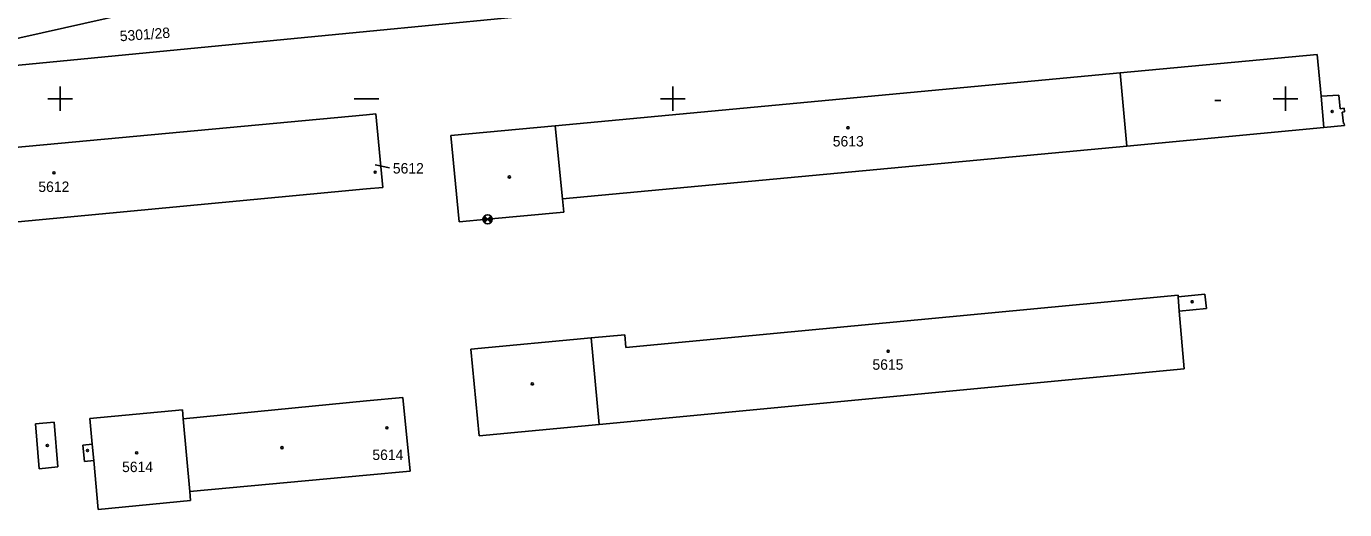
# Model space of a CAD drawing. Extents: x -822293 to -820259, y -1071573 to -1068794.
# Drawn here: x -821305.5 to -821090.3, y -1069967.1 to -1069888.2 of the extents above; entities that cross this region are included whole.
import ezdxf

# ---------------------------------------------------------------- set-up
doc = ezdxf.new("R2010")
doc.units = 0
for name, color, linetype in [('Vrstva 1', 7, 'Continuous'), ('Vrstva 10', 7, 'Continuous'), ('Vrstva 13', 7, 'Continuous'), ('Vrstva 18', 7, 'Continuous'), ('Vrstva 19', 7, 'Continuous'), ('Vrstva 2', 7, 'Continuous'), ('Vrstva 24', 7, 'Continuous'), ('Vrstva 25', 7, 'Continuous'), ('Vrstva 3', 7, 'Continuous'), ('Vrstva 62', 7, 'Continuous')]:
    doc.layers.add(name, color=color, linetype=linetype)

# ---------------------------------------------------------------- blocks, each defined once
blk = doc.blocks.new('02.04')
at = {"layer": 'Vrstva 1'}
for p, q in [((-2, 0), (2, 0)), ((0, -2), (0, 2))]:
    blk.add_line(p, q, dxfattribs=at)
blk = doc.blocks.new('02.05')
at = {"layer": 'Vrstva 1'}
blk.add_line((0, 0), (2, 0), dxfattribs=at)

msp = doc.modelspace()

# ---------------------------------------------------------------- linework, layer by layer
at = {"layer": 'Vrstva 1'}
msp.add_line((-821285.17, -1069885.29), (-821310.26, -1069890.87), dxfattribs=at)
at = {"layer": 'Vrstva 10'}
msp.add_line((-821248.56, -1069910.8), (-821246.25, -1069911.26), dxfattribs=at)
at = {"layer": 'Vrstva 13'}
for p, q in [((-821204.97, -1069884.66), (-821250, -1069889.013)), ((-821250, -1069889.013), (-821204.97, -1069884.66)), ((-821250, -1069889.013), (-821310.18, -1069894.83)), ((-821310.18, -1069894.83), (-821250, -1069889.013))]:
    msp.add_line(p, q, dxfattribs=at)
at = {"layer": 'Vrstva 2'}
for p, q in [((-821126.99, -1069895.8), (-821094.83, -1069892.79)), ((-821094.83, -1069892.79), (-821094.2, -1069899.61)), ((-821219.2, -1069904.42), (-821126.99, -1069895.8)), ((-821094.2, -1069899.61), (-821091.31, -1069899.42)), ((-821091.31, -1069899.42), (-821091.08, -1069901.64)), ((-821250, -1069902.622), (-821248.48, -1069902.48)), ((-821248.48, -1069902.48), (-821247.33, -1069914.47)), ((-821091.08, -1069901.64), (-821090.41, -1069901.57)), ((-821090.35, -1069902.14), (-821090.74, -1069902.17)), ((-821090.74, -1069902.17), (-821090.55, -1069904.06)), ((-821090.41, -1069901.57), (-821090.35, -1069902.14)), ((-821356.08, -1069912.51), (-821250, -1069902.622)), ((-821236.23, -1069906.01), (-821219.2, -1069904.42)), ((-821093.74, -1069904.69), (-821125.89, -1069907.73)), ((-821090.36, -1069904.37), (-821093.74, -1069904.69)), ((-821090.55, -1069904.06), (-821090.4, -1069904.04)), ((-821090.4, -1069904.04), (-821090.36, -1069904.37)), ((-821234.89, -1069920.11), (-821236.23, -1069906.01)), ((-821125.89, -1069907.73), (-821218, -1069916.36)), ((-821250, -1069914.722), (-821354.95, -1069924.62)), ((-821247.33, -1069914.47), (-821250, -1069914.722)), ((-821218, -1069916.36), (-821217.78, -1069918.52)), ((-821230.23, -1069919.68), (-821234.89, -1069920.11)), ((-821217.78, -1069918.52), (-821230.23, -1069919.68)), ((-821207.69, -1069940.62), (-821117.54, -1069932.09)), ((-821117.54, -1069932.09), (-821117.52, -1069932.34)), ((-821117.52, -1069932.34), (-821113.16, -1069931.9)), ((-821113.16, -1069931.9), (-821112.89, -1069934.23)), ((-821112.89, -1069934.23), (-821117.33, -1069934.69)), ((-821117.33, -1069934.69), (-821116.55, -1069944.11)), ((-821232.95, -1069940.9), (-821213.34, -1069939.04)), ((-821213.34, -1069939.04), (-821207.85, -1069938.52)), ((-821207.85, -1069938.52), (-821207.69, -1069940.62)), ((-821231.61, -1069955.04), (-821232.95, -1069940.9)), ((-821116.55, -1069944.11), (-821212.01, -1069953.18)), ((-821279.92, -1069952.26), (-821250, -1069949.339)), ((-821250, -1069949.339), (-821244.07, -1069948.76)), ((-821244.07, -1069948.76), (-821242.89, -1069960.8)), ((-821295.15, -1069952.17), (-821280.05, -1069950.77)), ((-821280.05, -1069950.77), (-821279.92, -1069952.26)), ((-821294.76, -1069956.41), (-821295.15, -1069952.17)), ((-821212.01, -1069953.18), (-821231.61, -1069955.04)), ((-821296.28, -1069956.55), (-821294.76, -1069956.41)), ((-821296.04, -1069959.2), (-821296.28, -1069956.55)), ((-821294.51, -1069959.06), (-821296.04, -1069959.2)), ((-821293.77, -1069967.07), (-821294.51, -1069959.06)), ((-821250, -1069961.455), (-821278.84, -1069964.11)), ((-821242.89, -1069960.8), (-821250, -1069961.455)), ((-821278.84, -1069964.11), (-821278.7, -1069965.6)), ((-821278.7, -1069965.6), (-821293.77, -1069967.07))]:
    msp.add_line(p, q, dxfattribs=at)
at = {"layer": 'Vrstva 24'}
for p, q in [((-821230.98, -1069919.68), (-821229.48, -1069919.68)), ((-821230.954, -1069919.486), (-821229.506, -1069919.874)), ((-821230.954, -1069919.874), (-821229.506, -1069919.486)), ((-821230.879, -1069919.305), (-821229.581, -1069920.055)), ((-821230.879, -1069920.055), (-821229.581, -1069919.305)), ((-821230.76, -1069920.21), (-821229.7, -1069919.15)), ((-821230.76, -1069919.15), (-821229.7, -1069920.21))]:
    msp.add_line(p, q, dxfattribs=at)
msp.add_circle((-821230.23, -1069919.68), 0.75, dxfattribs=at)
at = {"layer": 'Vrstva 25'}
msp.add_line((-821111.56, -1069900.29), (-821110.56, -1069900.29), dxfattribs=at)
for centre in [(-821092.38, -1069902.08), (-821171.41, -1069904.74), (-821301, -1069912.11), (-821248.58, -1069911.99), (-821226.67, -1069912.77), (-821115.23, -1069933.14), (-821164.85, -1069941.22), (-821222.93, -1069946.55), (-821246.66, -1069953.71), (-821302.08, -1069956.59), (-821295.53, -1069957.43), (-821287.5, -1069957.81), (-821263.79, -1069956.95)]:
    msp.add_circle(centre, 0.175, dxfattribs=at)
at = {"layer": 'Vrstva 3'}
for p, q in [((-821126.99, -1069895.8), (-821125.89, -1069907.73)), ((-821094.2, -1069899.61), (-821093.74, -1069904.69)), ((-821219.2, -1069904.42), (-821218, -1069916.36)), ((-821117.52, -1069932.34), (-821117.33, -1069934.69)), ((-821213.34, -1069939.04), (-821212.01, -1069953.18)), ((-821304.03, -1069953.05), (-821300.95, -1069952.82)), ((-821303.42, -1069960.39), (-821304.03, -1069953.05)), ((-821300.95, -1069952.82), (-821300.38, -1069960.11)), ((-821279.92, -1069952.26), (-821278.84, -1069964.11)), ((-821294.76, -1069956.41), (-821294.51, -1069959.06)), ((-821300.38, -1069960.11), (-821303.42, -1069960.39))]:
    msp.add_line(p, q, dxfattribs=at)
at = {"layer": 'Vrstva 62'}
msp.add_line((-821252, -1069900), (-821250, -1069900), dxfattribs=at)

# ---------------------------------------------------------------- block references
for name, p in [('02.04', (-821300, -1069900)), ('02.04', (-821200, -1069900)), ('02.04', (-821100, -1069900)), ('02.05', (-821250, -1069900))]:
    msp.add_blockref(name, p, dxfattribs=at)

# ---------------------------------------------------------------- texts
at = {"layer": 'Vrstva 18'}
msp.add_text('5301/28', height=1.7, rotation=4.10499, dxfattribs=at).set_placement((-821290.199, -1069890.636))
at = {"layer": 'Vrstva 19'}
for s, p in [('5613', (-821173.894, -1069907.8)), ('5612', (-821245.692, -1069912.21)), ('5612', (-821303.552, -1069915.22)), ('5615', (-821167.418, -1069944.24)), ('5614', (-821249.037, -1069958.97)), ('5614', (-821289.887, -1069960.94))]:
    msp.add_text(s, height=1.7, dxfattribs=at).set_placement(p)

doc.saveas('drawing.dxf')
